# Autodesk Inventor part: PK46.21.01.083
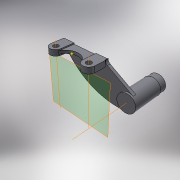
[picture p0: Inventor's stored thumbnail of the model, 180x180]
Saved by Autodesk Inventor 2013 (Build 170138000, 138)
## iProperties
Created: 2005-03
Part Number: PK46.21.01.083
Material: Steel, Mild
Document SubType Name: Modeling
Designer: salex
Manufacturer: Standard
Standards Organization: Custom
Density: 7.86 g/cm^3
Mass: 4464.91 g
Surface Area: 799.794 cm^2
Volume: 568.055 cm^3
Author: salex
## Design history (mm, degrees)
sketch "Эскиз1"
  geometry: L1 (73.452, 28.786)-(73.452, -16.214); L2 (-86.548, 28.786)-(73.452, 28.786); L3 (-86.548, -16.214)-(-86.548, 28.786); L4 (-32.806, 3.786)-(38.179, 3.786); A1 r 20 centre (53.452, -16.214) between (34.99, -23.906) and (73.452, -16.214); A2 r 20 centre (-66.548, -16.214) between (-86.548, -16.214) and (-48.087, -23.906); A3 r 45 centre (-6.548, -41.214) between (34.99, -23.906) and (-48.087, -23.906)
  constraints: 8 end point, 6 point on circle, 5 tangent, 3 centre point, 2 horizontal, 2 vertical, 1 other
  dimensions: "d1" = 120 distance of A2.centre A1.centre; "d3" = 45 radius of A3; "d5" = 45 vertical distance of A2.centre L2.start; "d7" = 25 vertical distance of L2.start L4.start
extrude "ExtrusionMidplane1" new body sketch "Эскиз1" stored distance "d8" = 10; taper "d9" = 0 deg
node "WorkAxis1"
node "WorkAxis2"
node "WorkPlane1"
node "WorkPlane2"
node "РабПлоскость3"
node "WorkPlane3"
sketch "Эскиз2"
  geometry: L1 (-86.548, 28.786)-(-86.548, -16.214); L2 (-46.548, 28.786)-(-86.548, 28.786); L3 (-46.548, -16.214)-(-46.548, 28.786); L4 (21.448, 28.786)-(20.448, 28.786); A1 r 20 centre (-66.548, -16.214) between (-86.548, -16.214) and (-46.548, -16.214); 1 further point
  constraints: 8 end point, 2 point on circle, 2 tangent, 2 vertical, 1 centre point, 1 coincident, 1 collinear, 1 horizontal, 1 horizontal alignment, 2 other
extrude "ExtrusionBlind1" join sketch "Эскиз2" distance "d14" = 19; taper "d15" = 0 deg
node "РабОсь3"
node "РабОсь4"
pattern_linear "RectArray1" dims "d18" = 120
sketch "Эскиз8"
  geometry: L1 (-100, 9)-(-140, 9) reference; L2 (-120, 9)-(-120, 47.073); C1 r 28 at (-216, -75)
  constraints: 2 end point, 1 centre point, 1 midpoint, 1 perpendicular
  dimensions: "d55" = 56 diameter of C1; "d152" = 96 distance from line of C1.centre L2; "d153" = 84 distance from line of C1.centre L1
extrude "ExtrusionBlind7" join sketch "Эскиз8" distance "d58" = 24; taper "d59" = 0 deg
sketch "Эскиз9"
  geometry: C1 r 29 at (-216, -75); C2 r 28 at (-216, -75); C3 r 28 at (-216, -75) reference
  constraints: 2 centre point, 1 coincident, 1 concentric
  dimensions: "d63" = 58 diameter of C1
extrude "ExtrusionBlind8" join sketch "Эскиз9" distance "d64" = 100; taper "d65" = 0 deg
sketch "Эскиз10"
  geometry: L1 (160, 15)-(160, -6.025); L2 (0.292, 15)-(160, 15); L3 (31.605, 28.83)-(20, 15); L4 (167.5, 6.965)-(250.5, 54.885); L5 (160, 38)-(160, 37); L6 (-40.894, 30)-(-39.894, 30); L7 (0, 38)-(0, 37); L8 (160, 15)-(160, -4) reference; L9 (160, 15)-(120, 15) reference; L10 (0, 15)-(0, -4) reference; L11 (160, 0)-(20, 0); L12 (20, 0)-(20, 15); L13 (40, 0)-(120, 0) reference; L14 (160, 10.803)-(160, 0); L15 (160, 0)-(160, 15); L16 (160, 0)-(20, 0); L17 (20, 15)-(160, 15); C1 r 29 at (236, 80); C2 r 29 at (236, 80) reference; A1 r 15 centre (175, -6.025) between (167.5, 6.965) and (160, -6.025); A2 r 230 centre (207.795, -119.011) between (240.069, 108.713) and (31.605, 28.83); A3 r 29 centre (236, 80) between (250.5, 54.885) and (240.069, 108.713)
  constraints: 26 end point, 7 collinear, 6 point on circle, 5 tangent, 4 centre point, 3 concentric, 3 perpendicular, 3 point on line, 1 coincident, 1 horizontal, 1 vertical
  dimensions: "d73" = 30 deg angle of L2 L4; "d154" = 15 radius of A1; "d156" = 230 radius of A2; "d157" = 20 distance of L3.end L10.start; "d158" = 50 deg angle of L2 L3
extrude "ExtrusionBlind9" join sketch "Эскиз10" distance "d77" = 10; taper "d78" = 0 deg
node "РабОсь8"
node "РабОсь11"
node "РабОсь12"
node "РабПлоскость12"
node "РабОсь13"
node "РабОсь14"
node "РабПлоскость13"
node "РабТочка2"
body "Solid1"
sketch "Эскиз16"
  geometry: A1 r 20 centre (-120, 0) between (-140, 0) and (-100, 0) reference; 1 further point
hole "Hole5" sketch "Эскиз16" diameter "d115" = 18; stored, may be unused: countersink angle "d119" = 90 deg, drill point angle "d121" = 118 deg; dims "d116" = 6, "d117" = 4, "d118" = 2, "d120" = 8
sketch "Эскиз17"
  geometry: A1 r 20 centre (0, 0) between (-20, 0) and (-18.462, -7.692) reference; 1 further point
hole "Hole6" sketch "Эскиз17" diameter "d122" = 18; stored, may be unused: countersink angle "d126" = 90 deg, drill point angle "d128" = 118 deg; dims "d123" = 6, "d124" = 4, "d125" = 2, "d127" = 8
other parameters: "d2" = 45 (derived), "d4" = 45 (derived), "d6" = 25 (derived), "d10" = 0, "d11" = 0, "d12" = -15, "d13" = -129, "d22" = 0, "d23" = 0, "d24" = 16 (derived), "d26" = 96 (derived), "d28" = 114 (derived), "d30" = 57 (derived), "d34" = 15 (derived), "d36" = 48 (derived), "d38" = 25 deg (derived), "d50" = 0, "d53" = 0, "d54" = 56 (derived), "d60" = 0, "d61" = 0, "d62" = 58 (derived), "d66" = 15 (derived), "d70" = 155 (derived), "d72" = 25 deg (derived), "d74" = 30 deg (derived), "d76" = 0 (derived), "d80" = 0 (derived), "d81" = 146 (derived), "d83" = 54 (derived), "d129" = 135 deg (derived), "d131" = 35 (derived), "d133" = 20.5 (derived), "d135" = 22.5 (derived), "d137" = 42 (derived), "d159" = 90 deg
